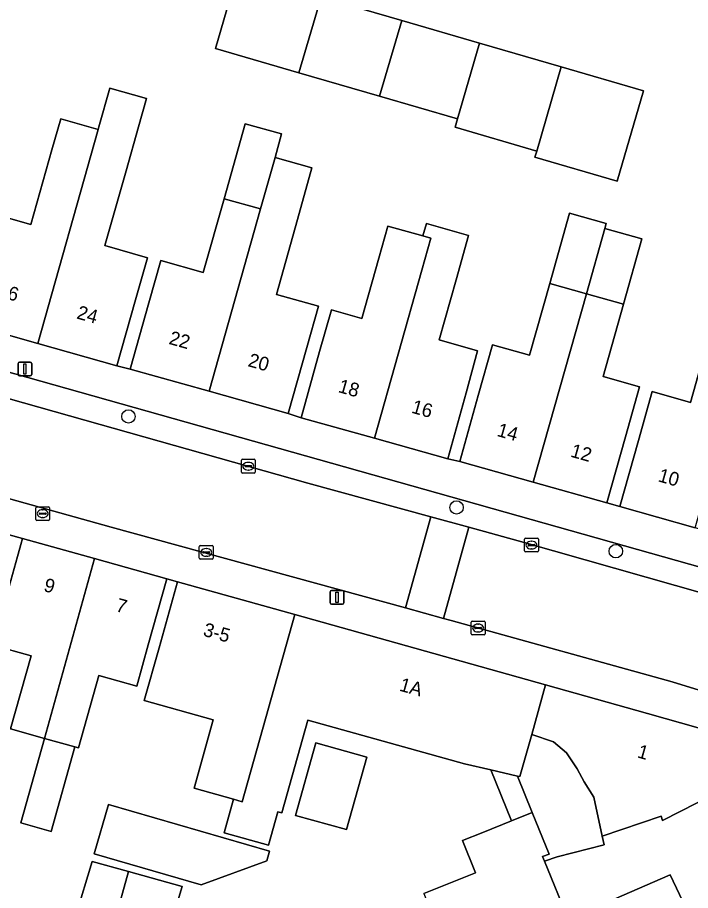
# Model space of a CAD drawing. Extents: x 158086 to 159499, y 382904 to 383981.
# Drawn here: x 158795.7 to 158844.7, y 383194.4 to 383258 of the extents above; entities that cross this region are included whole.
import ezdxf

# ---------------------------------------------------------------- set-up
doc = ezdxf.new("R2010")
doc.units = 0
for name, color, linetype in [('IMGEO_Boom', 7, 'Continuous'), ('IMGEO_Brandkraan', 7, 'Continuous'), ('IMGEO_Erf', 7, 'Continuous'), ('IMGEO_Kolk', 7, 'Continuous'), ('IMGEO_Lichtmast', 7, 'Continuous'), ('IMGEO_Pand', 7, 'Continuous'), ('IMGEO_Pand_nummerreeks', 7, 'Continuous'), ('IMGEO_Parkeervlak_open', 7, 'Continuous'), ('IMGEO_Rijbaan_lokaal_open', 7, 'Continuous'), ('IMGEO_Voetpad_open', 7, 'Continuous')]:
    doc.layers.add(name, color=color, linetype=linetype)

msp = doc.modelspace()

# ---------------------------------------------------------------- linework, layer by layer
at = {"layer": 'IMGEO_Boom'}
for centre in [(158803.776, 383228.915), (158827.661, 383222.288), (158839.255, 383219.104)]:
    msp.add_circle(centre, 0.489, dxfattribs=at)
at = {"layer": 'IMGEO_Brandkraan'}
for p, q in [((158797.034, 383221.411), (158797.034, 383222.263)), ((158797.109, 383222.337), (158797.961, 383222.337)), ((158798.035, 383222.263), (158798.035, 383221.411)), ((158797.293, 383221.831), (158797.293, 383221.843)), ((158797.731, 383221.794), (158797.333, 383221.794)), ((158797.336, 383221.88), (158797.734, 383221.88)), ((158797.522, 383222.117), (158797.547, 383222.117)), ((158797.777, 383221.843), (158797.777, 383221.831)), ((158797.961, 383221.337), (158797.109, 383221.337)), ((158797.545, 383221.557), (158797.52, 383221.557))]:
    msp.add_line(p, q, dxfattribs=at)
for points in [[(158797.034, 383221.411), (158797.034, 383222.263)], [(158797.109, 383222.337), (158797.961, 383222.337)], [(158798.035, 383222.263), (158798.035, 383221.411)], [(158797.961, 383221.337), (158797.109, 383221.337)]]:
    msp.add_lwpolyline(points, dxfattribs=at)
for centre, radius, start, end in [((158797.111, 383222.261), 0.0765, 91.55205, 178.44795), ((158797.111, 383222.261), 0.0765, 91.55205, 178.44795), ((158797.959, 383222.261), 0.0765, 1.55205, 88.44795), ((158797.959, 383222.261), 0.0765, 1.55205, 88.44795), ((158797.333, 383221.84), 0.0403, 85.87752, 175.75265), ((158797.33, 383221.83), 0.0366, 178.93798, 274.71019), ((158797.734, 383221.837), 0.043, 264.86636, 352.45326), ((158797.738, 383221.842), 0.0386, 1.73085, 96.63898), ((158797.111, 383221.413), 0.0765, 181.55205, 268.44795), ((158797.111, 383221.413), 0.0765, 181.55205, 268.44795), ((158797.959, 383221.413), 0.0765, 271.55205, 358.44795), ((158797.959, 383221.413), 0.0765, 271.55205, 358.44795)]:
    msp.add_arc(centre, radius, start, end, dxfattribs=at)
for centre, major_axis, ratio, start_param, end_param in [((158797.521, 383221.837), (-0.387, 0.002), 0.722429, 4.712389, 7.853982), ((158797.546, 383221.837), (-0.39, 0.002), 0.717154, 1.570796, 4.712389)]:
    msp.add_ellipse(centre, major_axis=major_axis, ratio=ratio, start_param=start_param, end_param=end_param, dxfattribs=at)
at = {"layer": 'IMGEO_Erf'}
for points in [[(158827.728, 383250.583), (158822.063, 383252.236), (158816.186, 383253.951), (158810.112, 383255.724), (158811.724, 383261.246), (158817.797, 383259.473), (158823.675, 383257.758), (158829.339, 383256.105), (158835.286, 383254.37), (158841.275, 383252.623), (158839.356, 383246.045), (158833.367, 383247.792), (158833.498, 383248.242), (158827.551, 383249.977)], [(158837.655, 383201.177), (158836.955, 383202.292), (158836.431, 383203.248), (158835.67, 383204.416), (158834.721, 383205.215), (158833.133, 383205.754), (158832.273, 383202.685), (158832.087, 383202.728), (158833.165, 383200.064), (158834.396, 383197.023), (158833.922, 383196.862), (158834.057, 383196.53), (158834.99, 383196.847), (158838.401, 383197.703), (158838.264, 383198.339)], [(158817.422, 383205.149), (158821.133, 383204.109), (158819.651, 383198.823), (158815.94, 383199.863)], [(158802.318, 383200.661), (158814.041, 383197.256), (158813.846, 383196.549), (158809.061, 383194.801), (158801.273, 383197.063)], [(158807.691, 383194.68), (158807.292, 383193.391), (158804.078, 383192.211), (158802.434, 383191.607), (158799.94, 383192.557), (158801.131, 383196.503), (158803.783, 383195.766)], [(158844.348, 383193.122), (158843.216, 383195.534), (158835.777, 383192.295), (158836.907, 383189.493)]]:
    msp.add_lwpolyline(points, close=True, dxfattribs=at)
for points in [[(158793.665, 383243.736), (158796.677, 383242.903), (158798.207, 383248.335), (158798.844, 383250.597), (158801.575, 383249.827), (158801.624, 383250), (158802.421, 383252.831), (158805.087, 383252.08), (158804.501, 383250), (158803.604, 383246.815), (158802.069, 383241.366), (158805.163, 383240.472), (158804.297, 383237.413), (158802.942, 383232.6), (158803.899, 383232.37), (158805.255, 383237.183), (158806.144, 383240.275), (158809.22, 383239.399), (158810.734, 383244.774), (158812.273, 383250.237), (158814.929, 383249.489), (158814.447, 383247.777), (158817.137, 383247.02), (158816.081, 383243.268), (158814.543, 383237.804), (158817.601, 383236.956), (158816.759, 383233.943), (158815.403, 383229.13), (158816.339, 383228.827), (158817.695, 383233.64), (158818.565, 383236.682), (158820.769, 383236.047), (158822.008, 383240.445), (158822.667, 383242.785), (158825.214, 383242.067), (158825.466, 383242.963), (158828.54, 383242.097), (158827.629, 383238.862), (158826.399, 383234.495), (158829.187, 383233.699), (158828.371, 383230.634), (158827.015, 383225.821), (158827.888, 383225.635), (158829.244, 383230.448), (158830.283, 383234.138), (158832.972, 383233.38), (158834.44, 383238.596), (158835.883, 383243.725), (158838.559, 383242.972), (158838.455, 383242.602), (158841.146, 383241.844), (158839.806, 383237.085), (158838.322, 383231.815), (158840.987, 383231.067), (158839.965, 383227.428), (158838.609, 383222.615), (158839.545, 383222.35), (158840.901, 383227.163), (158841.904, 383230.726), (158844.683, 383229.944), (158846.065, 383234.851)], [(158794.722, 383215.214), (158796.067, 383220.029), (158795.097, 383220.282)], [(158825.291, 383194.172), (158829.042, 383195.685), (158828.1, 383198.022), (158829.57, 383198.615), (158831.651, 383199.454), (158830.153, 383203.169), (158828.232, 383203.607), (158816.843, 383206.8), (158814.951, 383200.049), (158814.662, 383200.13), (158813.979, 383197.694), (158810.744, 383198.6), (158811.426, 383201.036), (158808.551, 383201.842), (158809.944, 383206.815), (158804.931, 383208.22), (158806.005, 383212.054), (158807.354, 383216.868), (158806.567, 383217.096), (158805.222, 383212.281), (158804.38, 383209.267), (158801.614, 383210.039), (158800.143, 383204.774), (158799.874, 383204.849), (158798.153, 383198.69), (158795.934, 383199.31), (158797.655, 383205.469), (158795.199, 383206.154), (158796.684, 383211.469), (158793.893, 383212.249)]]:
    msp.add_lwpolyline(points, dxfattribs=at)
at = {"layer": 'IMGEO_Kolk'}
for p, q in [((158812.002, 383224.868), (158812.002, 383225.72)), ((158812.077, 383225.794), (158812.929, 383225.794)), ((158812.49, 383225.574), (158812.515, 383225.574)), ((158813.003, 383225.72), (158813.003, 383224.868)), ((158812.929, 383224.794), (158812.077, 383224.794)), ((158812.261, 383225.288), (158812.261, 383225.3)), ((158812.699, 383225.251), (158812.301, 383225.251)), ((158812.304, 383225.337), (158812.702, 383225.337)), ((158812.513, 383225.014), (158812.488, 383225.014)), ((158812.745, 383225.3), (158812.745, 383225.288)), ((158832.615, 383219.12), (158832.615, 383219.972)), ((158832.69, 383220.046), (158833.542, 383220.046)), ((158833.103, 383219.826), (158833.128, 383219.826)), ((158833.616, 383219.972), (158833.616, 383219.12)), ((158808.937, 383218.589), (158808.937, 383219.441)), ((158809.012, 383219.515), (158809.864, 383219.515)), ((158809.239, 383219.058), (158809.637, 383219.058)), ((158809.425, 383219.295), (158809.45, 383219.295)), ((158809.938, 383219.441), (158809.938, 383218.589)), ((158833.542, 383219.046), (158832.69, 383219.046)), ((158832.874, 383219.54), (158832.874, 383219.552)), ((158833.312, 383219.503), (158832.914, 383219.503)), ((158832.917, 383219.589), (158833.315, 383219.589)), ((158833.126, 383219.266), (158833.101, 383219.266)), ((158833.358, 383219.552), (158833.358, 383219.54)), ((158809.864, 383218.515), (158809.012, 383218.515)), ((158809.196, 383219.009), (158809.196, 383219.021)), ((158809.634, 383218.972), (158809.236, 383218.972)), ((158809.448, 383218.735), (158809.423, 383218.735)), ((158809.68, 383219.021), (158809.68, 383219.009)), ((158828.809, 383214.006), (158829.661, 383214.006)), ((158828.734, 383213.08), (158828.734, 383213.932)), ((158828.993, 383213.5), (158828.993, 383213.512)), ((158829.431, 383213.463), (158829.033, 383213.463)), ((158829.036, 383213.549), (158829.434, 383213.549)), ((158829.222, 383213.786), (158829.247, 383213.786)), ((158829.477, 383213.512), (158829.477, 383213.5)), ((158829.735, 383213.932), (158829.735, 383213.08)), ((158829.661, 383213.006), (158828.809, 383213.006)), ((158829.245, 383213.226), (158829.22, 383213.226))]:
    msp.add_line(p, q, dxfattribs=at)
for points in [[(158812.002, 383224.868), (158812.002, 383225.72)], [(158812.077, 383225.794), (158812.929, 383225.794)], [(158813.003, 383225.72), (158813.003, 383224.868)], [(158812.929, 383224.794), (158812.077, 383224.794)], [(158832.615, 383219.12), (158832.615, 383219.972)], [(158832.69, 383220.046), (158833.542, 383220.046)], [(158833.616, 383219.972), (158833.616, 383219.12)], [(158808.937, 383218.589), (158808.937, 383219.441)], [(158809.012, 383219.515), (158809.864, 383219.515)], [(158809.938, 383219.441), (158809.938, 383218.589)], [(158833.542, 383219.046), (158832.69, 383219.046)], [(158809.864, 383218.515), (158809.012, 383218.515)], [(158828.809, 383214.006), (158829.661, 383214.006)], [(158828.734, 383213.08), (158828.734, 383213.932)], [(158829.735, 383213.932), (158829.735, 383213.08)], [(158829.661, 383213.006), (158828.809, 383213.006)]]:
    msp.add_lwpolyline(points, dxfattribs=at)
for centre, radius, start, end in [((158812.079, 383225.718), 0.0765, 91.55205, 178.44795), ((158812.079, 383225.718), 0.0765, 91.55205, 178.44795), ((158812.927, 383225.718), 0.0765, 1.55205, 88.44795), ((158812.927, 383225.718), 0.0765, 1.55205, 88.44795), ((158812.079, 383224.87), 0.0765, 181.55205, 268.44795), ((158812.079, 383224.87), 0.0765, 181.55205, 268.44795), ((158812.301, 383225.297), 0.0403, 85.87752, 175.75265), ((158812.298, 383225.287), 0.0366, 178.93798, 274.71019), ((158812.702, 383225.294), 0.043, 264.86636, 352.45326), ((158812.706, 383225.299), 0.0386, 1.73085, 96.63898), ((158812.927, 383224.87), 0.0765, 271.55205, 358.44795), ((158812.927, 383224.87), 0.0765, 271.55205, 358.44795), ((158832.692, 383219.97), 0.0765, 91.55205, 178.44795), ((158832.692, 383219.97), 0.0765, 91.55205, 178.44795), ((158833.54, 383219.97), 0.0765, 1.55205, 88.44795), ((158833.54, 383219.97), 0.0765, 1.55205, 88.44795), ((158809.014, 383219.439), 0.0765, 91.55205, 178.44795), ((158809.014, 383219.439), 0.0765, 91.55205, 178.44795), ((158809.236, 383219.018), 0.0403, 85.87752, 175.75265), ((158809.641, 383219.02), 0.0386, 1.73085, 96.63898), ((158809.862, 383219.439), 0.0765, 1.55205, 88.44795), ((158809.862, 383219.439), 0.0765, 1.55205, 88.44795), ((158832.692, 383219.122), 0.0765, 181.55205, 268.44795), ((158832.692, 383219.122), 0.0765, 181.55205, 268.44795), ((158832.914, 383219.549), 0.0403, 85.87752, 175.75265), ((158832.911, 383219.539), 0.0366, 178.93798, 274.71019), ((158833.315, 383219.546), 0.043, 264.86636, 352.45326), ((158833.319, 383219.551), 0.0386, 1.73085, 96.63898), ((158833.54, 383219.122), 0.0765, 271.55205, 358.44795), ((158833.54, 383219.122), 0.0765, 271.55205, 358.44795), ((158809.014, 383218.591), 0.0765, 181.55205, 268.44795), ((158809.014, 383218.591), 0.0765, 181.55205, 268.44795), ((158809.233, 383219.008), 0.0366, 178.93798, 274.71019), ((158809.637, 383219.015), 0.043, 264.86636, 352.45326), ((158809.862, 383218.591), 0.0765, 271.55205, 358.44795), ((158809.862, 383218.591), 0.0765, 271.55205, 358.44795), ((158828.811, 383213.93), 0.0765, 91.55205, 178.44795), ((158828.811, 383213.93), 0.0765, 91.55205, 178.44795), ((158829.659, 383213.93), 0.0765, 1.55205, 88.44795), ((158829.659, 383213.93), 0.0765, 1.55205, 88.44795), ((158829.033, 383213.509), 0.0403, 85.87752, 175.75265), ((158829.03, 383213.499), 0.0366, 178.93798, 274.71019), ((158829.434, 383213.506), 0.043, 264.86636, 352.45326), ((158829.438, 383213.511), 0.0386, 1.73085, 96.63898), ((158828.811, 383213.082), 0.0765, 181.55205, 268.44795), ((158828.811, 383213.082), 0.0765, 181.55205, 268.44795), ((158829.659, 383213.082), 0.0765, 271.55205, 358.44795), ((158829.659, 383213.082), 0.0765, 271.55205, 358.44795)]:
    msp.add_arc(centre, radius, start, end, dxfattribs=at)
for centre, major_axis, ratio, start_param, end_param in [((158812.489, 383225.294), (-0.387, 0.002), 0.722429, 4.712389, 7.853982), ((158812.514, 383225.294), (-0.39, 0.002), 0.717154, 1.570796, 4.712389), ((158833.102, 383219.546), (-0.387, 0.002), 0.722429, 4.712389, 7.853982), ((158833.127, 383219.546), (-0.39, 0.002), 0.717154, 1.570796, 4.712389), ((158809.424, 383219.015), (-0.387, 0.002), 0.722429, 4.712389, 7.853982), ((158809.449, 383219.015), (-0.39, 0.002), 0.717154, 1.570796, 4.712389), ((158829.221, 383213.506), (-0.387, 0.002), 0.722429, 4.712389, 7.853982), ((158829.246, 383213.506), (-0.39, 0.002), 0.717154, 1.570796, 4.712389)]:
    msp.add_ellipse(centre, major_axis=major_axis, ratio=ratio, start_param=start_param, end_param=end_param, dxfattribs=at)
at = {"layer": 'IMGEO_Lichtmast'}
for p, q in [((158795.745, 383231.97), (158795.745, 383232.77)), ((158795.745, 383232.77), (158795.745, 383231.97)), ((158795.845, 383232.87), (158796.635, 383232.87)), ((158796.635, 383232.87), (158795.845, 383232.87)), ((158796.735, 383232.77), (158796.735, 383231.97)), ((158796.735, 383231.97), (158796.735, 383232.77)), ((158796.635, 383231.87), (158795.845, 383231.87)), ((158795.845, 383231.87), (158796.635, 383231.87)), ((158818.465, 383215.336), (158818.465, 383216.136)), ((158818.465, 383216.136), (158818.465, 383215.336)), ((158818.565, 383216.236), (158819.355, 383216.236)), ((158819.355, 383216.236), (158818.565, 383216.236)), ((158819.455, 383216.136), (158819.455, 383215.336)), ((158819.455, 383215.336), (158819.455, 383216.136)), ((158819.355, 383215.236), (158818.565, 383215.236)), ((158818.565, 383215.236), (158819.355, 383215.236))]:
    msp.add_line(p, q, dxfattribs=at)
for points in [[(158796.165, 383232.745), (158796.315, 383232.745), (158796.315, 383231.995), (158796.165, 383231.995), (158796.165, 383232.745)], [(158818.885, 383216.111), (158819.035, 383216.111), (158819.035, 383215.361), (158818.885, 383215.361), (158818.885, 383216.111)]]:
    msp.add_lwpolyline(points, dxfattribs=at)
for centre, start, end in [((158795.845, 383232.77), 90, 180), ((158795.845, 383232.77), 90, 180), ((158796.635, 383232.77), 0, 90), ((158796.635, 383232.77), 360, 90), ((158795.845, 383231.97), 180, 270), ((158795.845, 383231.97), 180, 270), ((158796.635, 383231.97), 270, 0), ((158796.635, 383231.97), 270, 0), ((158818.565, 383216.136), 90, 180), ((158818.565, 383216.136), 90, 180), ((158819.355, 383216.136), 0, 90), ((158819.355, 383216.136), 360, 90), ((158818.565, 383215.336), 180, 270), ((158818.565, 383215.336), 180, 270), ((158819.355, 383215.336), 270, 0), ((158819.355, 383215.336), 270, 0)]:
    msp.add_arc(centre, 0.1, start, end, dxfattribs=at)
at = {"layer": 'IMGEO_Pand'}
for points in [[(158817.797, 383259.473), (158811.724, 383261.246), (158810.112, 383255.724), (158816.186, 383253.951)], [(158823.675, 383257.758), (158817.797, 383259.473), (158816.186, 383253.951), (158822.063, 383252.236)], [(158829.339, 383256.105), (158823.675, 383257.758), (158822.063, 383252.236), (158827.728, 383250.583)], [(158829.339, 383256.105), (158827.728, 383250.583), (158827.551, 383249.977), (158833.498, 383248.242), (158835.286, 383254.37)], [(158835.286, 383254.37), (158833.498, 383248.242), (158833.367, 383247.792), (158839.356, 383246.045), (158841.275, 383252.623)], [(158797.18, 383234.223), (158802.942, 383232.6), (158804.297, 383237.413), (158805.163, 383240.472), (158802.069, 383241.366), (158803.604, 383246.815), (158804.501, 383250), (158805.087, 383252.08), (158802.421, 383252.831), (158801.624, 383250), (158801.575, 383249.827)], [(158797.18, 383234.223), (158801.575, 383249.827), (158798.844, 383250.597), (158798.207, 383248.335), (158796.677, 383242.903), (158793.665, 383243.736), (158792.777, 383240.658), (158791.421, 383235.845)], [(158814.447, 383247.777), (158814.929, 383249.489), (158812.273, 383250.237), (158810.734, 383244.774), (158813.391, 383244.026)], [(158809.652, 383230.75), (158815.403, 383229.13), (158816.759, 383233.943), (158817.601, 383236.956), (158814.543, 383237.804), (158816.081, 383243.268), (158817.137, 383247.02), (158814.447, 383247.777), (158813.391, 383244.026)], [(158809.652, 383230.75), (158813.391, 383244.026), (158810.734, 383244.774), (158809.22, 383239.399), (158806.144, 383240.275), (158805.255, 383237.183), (158803.899, 383232.37)], [(158838.455, 383242.602), (158838.559, 383242.972), (158835.883, 383243.725), (158834.44, 383238.596), (158837.114, 383237.843)], [(158825.124, 383239.567), (158825.783, 383241.907), (158825.214, 383242.067), (158822.667, 383242.785), (158822.008, 383240.445), (158820.769, 383236.047), (158818.565, 383236.682), (158817.695, 383233.64), (158816.339, 383228.827), (158821.678, 383227.324)], [(158825.214, 383242.067), (158825.783, 383241.907), (158825.124, 383239.567), (158821.678, 383227.324), (158827.015, 383225.821), (158828.371, 383230.634), (158829.187, 383233.699), (158826.399, 383234.495), (158827.629, 383238.862), (158828.54, 383242.097), (158825.466, 383242.963)], [(158838.455, 383242.602), (158837.114, 383237.843), (158839.806, 383237.085), (158841.146, 383241.844)], [(158833.25, 383224.125), (158837.114, 383237.843), (158834.44, 383238.596), (158832.972, 383233.38), (158830.283, 383234.138), (158829.244, 383230.448), (158827.888, 383225.635)], [(158833.25, 383224.125), (158838.609, 383222.615), (158839.965, 383227.428), (158840.987, 383231.067), (158838.322, 383231.815), (158839.806, 383237.085), (158837.114, 383237.843)], [(158848.78, 383234.086), (158846.065, 383234.851), (158844.683, 383229.944), (158841.904, 383230.726), (158840.901, 383227.163), (158839.545, 383222.35), (158845.038, 383220.803)], [(158801.315, 383218.563), (158796.067, 383220.029), (158794.722, 383215.214), (158793.893, 383212.249), (158796.684, 383211.469), (158795.199, 383206.154), (158797.655, 383205.469)], [(158805.222, 383212.281), (158806.567, 383217.096), (158801.315, 383218.563), (158797.655, 383205.469), (158799.874, 383204.849), (158800.143, 383204.774), (158801.614, 383210.039), (158804.38, 383209.267)], [(158815.88, 383214.479), (158807.354, 383216.868), (158806.005, 383212.054), (158804.931, 383208.22), (158809.944, 383206.815), (158808.551, 383201.842), (158811.426, 383201.036), (158812.062, 383200.858)], [(158834.144, 383209.36), (158815.88, 383214.479), (158812.062, 383200.858), (158811.426, 383201.036), (158810.744, 383198.6), (158813.979, 383197.694), (158814.662, 383200.13), (158814.951, 383200.049), (158816.843, 383206.8), (158828.232, 383203.607), (158830.153, 383203.169), (158832.087, 383202.728), (158832.273, 383202.685), (158833.133, 383205.754)], [(158834.144, 383209.36), (158833.133, 383205.754), (158834.721, 383205.215), (158835.67, 383204.416), (158836.431, 383203.248), (158836.955, 383202.292), (158837.655, 383201.177), (158838.264, 383198.339), (158842.559, 383199.8), (158842.663, 383199.497), (158848.995, 383202.716), (158847.662, 383205.563), (158841.551, 383207.276)], [(158799.874, 383204.849), (158797.655, 383205.469), (158795.934, 383199.31), (158798.153, 383198.69)], [(158815.94, 383199.863), (158819.651, 383198.823), (158821.133, 383204.109), (158817.422, 383205.149)], [(158832.087, 383202.728), (158830.153, 383203.169), (158831.651, 383199.454), (158833.165, 383200.064)], [(158848.995, 383202.716), (158842.663, 383199.497), (158842.559, 383199.8), (158838.264, 383198.339), (158838.401, 383197.703), (158834.99, 383196.847), (158834.057, 383196.53), (158835.777, 383192.295), (158843.216, 383195.534), (158844.348, 383193.122), (158851.841, 383196.636)], [(158801.273, 383197.063), (158809.061, 383194.801), (158813.846, 383196.549), (158814.041, 383197.256), (158802.318, 383200.661)], [(158834.057, 383196.53), (158833.922, 383196.862), (158834.396, 383197.023), (158833.165, 383200.064), (158831.651, 383199.454), (158829.57, 383198.615), (158828.1, 383198.022), (158829.042, 383195.685), (158825.291, 383194.172), (158828.561, 383186.11), (158836.907, 383189.493), (158835.777, 383192.295)], [(158803.783, 383195.766), (158801.131, 383196.503), (158799.94, 383192.557), (158802.434, 383191.607), (158804.078, 383192.211), (158803.88, 383192.578), (158802.778, 383192.175)], [(158807.691, 383194.68), (158803.783, 383195.766), (158802.778, 383192.175), (158803.88, 383192.578), (158804.078, 383192.211), (158807.292, 383193.391)]]:
    msp.add_lwpolyline(points, close=True, dxfattribs=at)
at = {"layer": 'IMGEO_Parkeervlak_open'}
for points in [[(158713.92, 383252.998), (158763.779, 383238.923), (158766.515, 383238.164), (158767.383, 383237.924), (158792.938, 383230.817), (158816.826, 383224.045), (158825.794, 383221.597), (158828.554, 383220.844), (158832.582, 383219.745), (158854.617, 383213.465)], [(158852.366, 383215.967), (158751.096, 383244.547), (158736.759, 383248.525)]]:
    msp.add_lwpolyline(points, dxfattribs=at)
at = {"layer": 'IMGEO_Rijbaan_lokaal_open'}
for points in [[(158766.515, 383238.164), (158764.65, 383231.517), (158766.719, 383230.948), (158783.113, 383226.274), (158802.524, 383220.86), (158823.947, 383214.968), (158825.794, 383221.597), (158816.826, 383224.045), (158792.938, 383230.817), (158767.383, 383237.924)], [(158828.554, 383220.844), (158825.794, 383221.597), (158823.947, 383214.968), (158826.704, 383214.209)]]:
    msp.add_lwpolyline(points, close=True, dxfattribs=at)
msp.add_lwpolyline([(158859.741, 383212.033), (158854.617, 383213.465), (158832.582, 383219.745), (158828.554, 383220.844), (158826.704, 383214.209), (158827.261, 383214.056), (158843.357, 383209.594), (158849.117, 383207.804)], dxfattribs=at)
at = {"layer": 'IMGEO_Voetpad_open'}
for points in [[(158717.528, 383253.943), (158733.654, 383249.4), (158733.773, 383249.834), (158736.878, 383248.959), (158736.759, 383248.525), (158751.096, 383244.547), (158852.366, 383215.967)], [(158849.117, 383207.804), (158843.357, 383209.594), (158827.261, 383214.056), (158826.704, 383214.209), (158823.947, 383214.968), (158802.524, 383220.86), (158783.113, 383226.274), (158766.719, 383230.948), (158764.65, 383231.517), (158761.912, 383232.269), (158712.045, 383246.282)], [(158876.476, 383211.724), (158875.416, 383212.025), (158866.813, 383214.468), (158866.865, 383214.646), (158865.944, 383214.9), (158857.12, 383217.385), (158851.448, 383218.983), (158850.532, 383219.256), (158845.038, 383220.803), (158839.545, 383222.35), (158838.609, 383222.615), (158833.25, 383224.125), (158827.888, 383225.635), (158827.015, 383225.821), (158821.678, 383227.324), (158816.339, 383228.827), (158815.403, 383229.13), (158809.652, 383230.75), (158803.899, 383232.37), (158802.942, 383232.6), (158797.18, 383234.223), (158791.421, 383235.845)], [(158795.097, 383220.282), (158796.067, 383220.029), (158801.315, 383218.563), (158806.567, 383217.096), (158807.354, 383216.868), (158815.88, 383214.479), (158834.144, 383209.36), (158841.551, 383207.276), (158847.662, 383205.563), (158848.995, 383202.716), (158851.841, 383196.636), (158856.736, 383199.923), (158855.249, 383203.088)]]:
    msp.add_lwpolyline(points, dxfattribs=at)

# ---------------------------------------------------------------- texts
at = {"layer": 'IMGEO_Pand_nummerreeks'}
for s, rotation, p in [('26', 344.26962, (158794.189, 383237.683)), ('24', 344.26962, (158799.95, 383236.061)), ('22', 344.27059, (158806.66, 383234.21)), ('20', 344.27059, (158812.418, 383232.588)), ('18', 344.27231, (158818.985, 383230.701)), ('16', 344.27231, (158824.32, 383229.198)), ('14', 344.26799, (158830.544, 383227.504)), ('12', 344.26799, (158835.901, 383225.995)), ('10', 344.27249, (158842.27, 383224.201)), ('9', 344.39318, (158797.545, 383216.211)), ('7', 344.39263, (158802.794, 383214.744)), ('3-5', 344.34704, (158809.151, 383212.958)), ('1A', 344.34106, (158823.44, 383208.953)), ('1', 344.34106, (158840.759, 383204.093))]:
    msp.add_text(s, height=1, rotation=rotation, dxfattribs=at).set_placement(p)

doc.saveas('drawing.dxf')
